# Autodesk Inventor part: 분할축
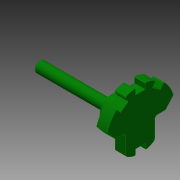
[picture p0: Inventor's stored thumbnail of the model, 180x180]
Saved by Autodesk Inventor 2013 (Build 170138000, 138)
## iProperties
Created: 2016-11
Part Number: 분할축
Material: 강철, 연강
Document SubType Name: Modeling
Designer: mduedu
Density: 1 g/cm^3
Author: mduedu
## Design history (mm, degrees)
sketch "스케치1"
  geometry: C1 r 38 at (0, 0); 1 further point
  constraints: 1 centre point, 1 coincident
  dimensions: "d0" = 76 diameter of C1
extrude "돌출1" new body sketch "스케치1" distance "d1" = 12; taper "d2" = 0 deg
sketch "스케치2"
  geometry: L1 (0, 38)-(0, -38); L2 (5.5, 37.6)-(5.5, 31); L3 (5.5, 31)-(-5.5, 31); L4 (-5.5, 31)-(-5.5, 37.6); A1 r 38 centre (0, 0) between (0, 38) and (0, -38) reference; A2 r 38 centre (0, 0) between (5.5, 37.6) and (-5.5, 37.6); 2 further points
  constraints: 8 end point, 6 point on circle, 2 coincident, 2 vertical, 1 centre point, 1 horizontal, 1 midpoint, 1 parallel, 1 symmetric about line
  dimensions: "d3" = 11 distance of L2.end L3.end; "d5" = 31 distance from line of L3 point (0, 0)
extrude "돌출2" cut sketch "스케치2" stored distance "d7" = 12; taper "d8" = 0 deg
sketch "스케치3"
  geometry: L1 (-16, 0)-(-38, 0); L2 (16, 0)-(38, 0); L3 (0, -28)-(0, 28); L4 (-16, -22.978)-(-16, 0); L5 (16, -22.978)-(16, 0); A1 r 38 centre (0, 0) between (-5.5, 37.6) and (-17.061, 33.955) reference; A2 r 38 centre (0, 0) between (-38, 0) and (38, 0); A3 r 28 centre (0, 0) between (-16, -22.978) and (16, -22.978); 4 further points
  constraints: 10 end point, 7 point on circle, 3 coincident, 2 centre point, 2 horizontal alignment, 2 midpoint, 2 parallel, 1 collinear, 1 horizontal, 1 perpendicular, 1 other
  dimensions: "d13" = 32 distance between parallel lines of L5 L4; "d14" = 28 radius of A3
extrude "돌출3" cut sketch "스케치3" stored distance "d15" = 12; taper "d16" = 0 deg
sketch "스케치4"
  geometry: L1 (0, 0)-(0, -28); L2 (5.5, -27.455)-(5.5, -21); L3 (5.5, -21)-(-5.5, -21); L4 (-5.5, -21)-(-5.5, -27.455); A1 r 28 centre (0, 0) between (-16, -22.978) and (16, -22.978) reference; A2 r 28 centre (0, 0) between (16, -22.978) and (0, -28); A3 r 28 centre (0, 0) between (-5.5, -27.455) and (5.5, -27.455); 1 further point
  constraints: 8 end point, 7 point on circle, 2 centre point, 2 coincident, 1 horizontal, 1 parallel, 1 other
  dimensions: "d17" = 11 distance between parallel lines of L2 L4; "d19" = 21 distance from line of L3 point (0, 0)
extrude "돌출4" cut sketch "스케치4" stored distance "d20" = 12; taper "d21" = 0 deg
sketch "스케치5"
  geometry: C1 r 13 at (0, 0); 1 further point
  constraints: 1 centre point, 1 coincident
  dimensions: "d22" = 26 diameter of C1
extrude "돌출5" join sketch "스케치5" distance "d23" = 20; taper "d24" = 0 deg
sketch "스케치6"
  geometry: C1 r 6 at (0, 0); 1 further point
  constraints: 1 centre point, 1 coincident
  dimensions: "d25" = 12 diameter of C1
extrude "돌출6" join sketch "스케치6" distance "d26" = 80; taper "d27" = 0 deg
fillet "모깎기1" dims "d28" = 3
chamfer "모따기1" distance "d29" = 1; stored, may be unused: second distance "d30" = 2, angle "d31" = 45 deg
sketch "스케치7"
  geometry: L1 (-20, 13)-(-20, -13) reference; L2 (-20, 6)-(-99, 6) reference; L3 (0, 0)-(-20, 0); C1 r 1 at (-21, 6)
  constraints: 2 end point, 1 centre point, 1 midpoint, 1 tangent
  dimensions: "d32" = 2 diameter of C1; "d33" = 10 dimension on C1 L3
revolve "회전1" sketch "스케치7" stored, may be unused: angle "d34" = 90 deg
chamfer "모따기2" distance "d35" = 1; stored, may be unused: second distance "d36" = 2, angle "d37" = 45 deg
chamfer "모따기3" distance "d38" = 10; stored, may be unused: second distance "d39" = 2, angle "d40" = 45 deg
chamfer "모따기4" distance "d41" = 1; stored, may be unused: second distance "d42" = 2, angle "d43" = 45 deg
fillet "모깎기2" dims "d44" = 3
node "솔리드1"
pattern_circular "원형 패턴1" dims angle "d10" = 35 deg
other parameters: "d12" = 56
